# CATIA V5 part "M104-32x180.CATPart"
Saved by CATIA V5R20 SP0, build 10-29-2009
Part number: M104-32x180
Source: Unknown
Bounding box of the stored display mesh (mm): x -15.868 to 15.868, y -15.868 to 15.868, z 0 to 180
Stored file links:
  C:\Users\Utente\Desktop\IO LAVORO\3D X SITO CF\X SITO\M104\M104-32x180.CATPart

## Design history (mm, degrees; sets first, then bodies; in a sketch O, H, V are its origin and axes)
Body1 (main body)
  Solid1 "PartBody": solid without history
